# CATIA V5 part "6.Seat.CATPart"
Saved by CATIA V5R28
Part number: Seat
Bounding box of the stored display mesh (mm): x -115 to 115, y -85.091 to 85.091, z -146.629 to 45.921
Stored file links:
  D:\Catia Cycle design\6.Seat.CATPart
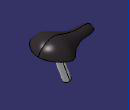
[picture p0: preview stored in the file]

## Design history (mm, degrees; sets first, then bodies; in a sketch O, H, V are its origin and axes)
Set1
  Sketch1 on xy-plane, origin (0, 0, 0), H (1, 0, 0), V (0, 1, 0)
    construction line L1 (115, 85) -> (115, -85)
    construction line L2 (115, -85) -> (-115, -85)
    construction line L3 (-115, -85) -> (-115, 85)
    construction line L4 (-115, 85) -> (115, 85)
    construction line L5 (-115, 85) -> (115, -85)
    construction line L6 (-115, -85) -> (115, 85)
    construction line L7 (-115, 0) -> (115, 0)
    point P5 (-115, 0)
    point P6 (115, 0)
    axis line L8 (0, 85) -> (0, -85)
    point P7 (0, 85)
    point P8 (0, -85)
    spline S1 through (-115, 0) (-108, -16) (-75, -25.5) (-40, -30) (-15, -40) (15, -60) (50, -85) (87.9412, -65) (109, -30) (115, 0)
    spline S2 through (-115, 0) (-108, 16) (-75, 25.5) (-40, 30) (-15, 40) (15, 60) (50, 85) (87.9412, 65) (109, 30) (115, 0)
    point P9 (-115, 0)
    point P10 (-40, -30)
    point P11 (50, -85)
    point P12 (87.9412, -65)
    point P13 (115, 0)
    point P14 (-108, -16)
    point P15 (-75, -25.5)
    point P16 (-15, -40)
    point P17 (15, -60)
    point P18 (109, -30)
    point P19 (115, 0)
    point P20 (-115, 0)
    point P21 (109, 30)
    point P22 (87.9412, 65)
    point P23 (50, 85)
    point P24 (15, 60)
    point P25 (-15, 40)
    point P26 (-40, 30)
    point P27 (-75, 25.5)
    point P28 (-108, 16)
    length L4 = 230
    length L1 = 170
    distance P14 L7 = 16
    distance P14 L3 = 7
    distance P15 L7 = 25.5
    distance P15 L3 = 40
    distance P10 L7 = 30
    distance P10 L3 = 75
    distance P16 L7 = 40
    distance P16 L3 = 100
    distance P17 L7 = 60
    distance P17 L3 = 130
    distance P11 L1 = 65
    distance P12 L7 = 65
    distance P18 L7 = 30
    distance P18 L1 = 6
    vertical: L1 V, L3 V, L8 V
    horizontal: L2 H, L4 H, L7 H
    equidistance: L1 L3 O, L2 L4 O
    midpoint: P5 L3, P6 L1, P7 L4, P8 L2
    coincidence: P9 P5, P11 L2, P12 L5, P13 P6
    symmetry: S1 S2 L7, P13 P19 L7, P9 P20 L7, P18 P21 L7, P12 P22 L7, P11 P23 L7, P17 P24 L7, P16 P25 L7, P10 P26 L7, P15 P27 L7, P14 P28 L7
  Sketch2 on zx-plane, origin (0, 0, 0), H (-1, 0, 0), V (0, 0, 1)
    spline S1 through (115, 0) (100, 18) (65, 21) (19, 25) (-14, 36) (-46, 45) (-85, 36) (-115, 0)
    reference projected line E1 (-115, 0) -> (115, 0) from Sketch1.S2
    reference projected line E2 (-115, 0) -> (115, 0) from Sketch1.S2
    reference projected line E3 (-115, 0) -> (115, 0) from Sketch1.S2
    reference projected line E4 (-115, 0) -> (115, 0) from Sketch1.S2
    reference projected line E5 (-115, 0) -> (115, 0) from Sketch1.S2
    reference projected line E6 (-115, 0) -> (115, 0) from Sketch1.S2
    reference projected line E7 (-115, 0) -> (115, 0) from Sketch1.S2
    point P1 (115, 0)
    point P2 (-115, 0)
    point P3 (-85, 36)
    point P4 (-46, 45)
    point P5 (-14, 36)
    point P6 (19, 25)
    point P7 (65, 21)
    point P8 (100, 18)
    distance V P2 = 115
    distance P3 E1 = 36
    distance P3 V = 85
    distance P4 E2 = 45
    distance P4 V = 46
    distance P5 V = 14
    distance P5 E3 = 36
    distance P6 V = 19
    distance P6 E4 = 25
    distance P7 E5 = 21
    distance P7 V = 65
    distance P8 E6 = 18
    distance P8 V = 100
    distance V P1 = 115
    distance P1 E7 = 0
    coincidence: P2 H
  DatumCurve1
  DatumCurve2
  Line1: type PtPt, FirstPoint Sketch2.P1, SecondPoint Sketch2.P2
  Plane1: type Offset, RefPlane yz-plane, Offset 108
  Plane2: type Offset, RefPlane yz-plane, Offset 80
  Plane3: type Offset, RefPlane yz-plane, Offset 50
  Plane4: type Offset, RefPlane yz-plane, Offset 40, reversed
  Plane5: type Offset, RefPlane yz-plane, Offset 80, reversed
  Plane6: type Offset, RefPlane yz-plane, Offset 110, reversed
  MultiSel1
  Sketch3 on Plane1, origin (108, 0, 0), H (0, 1, 0), V (0, 0, 1)
    arc A1 centre (0, -28.3932) radius 43.2124 from (-32.5751, 0) to (0, 14.8192) cw
    point P2 (-32.5751, 0)
    point P3 (0, 14.8192)
    reference projected point E1 (0, 14.8192) from {intersect ToIntersect1 Sketch2, ToIntersect2 Plane1}
    reference projected point E2 (-32.5751, 0) from {intersect ToIntersect1 DatumCurve2, ToIntersect2 Plane1}
    axis line L1 (0, 14.8192) -> (33.2132, 14.8192)
    line L2 (-32.5751, 0) -> (0, 0)
    line L3 (0, 0) -> (0, 14.8192)
    coincidence: P2 H, P3 V, P3 E1, P2 E2
    horizontal: L1 H, L2 H
    tangency: A1 L1
    vertical: L3 V
  MultiSel2
  Sketch4 on Plane3, origin (50, 0, 0), H (0, 1, 0), V (0, 0, 1)
    arc A1 centre (-0.0002, -57.2359) radius 102.474 from (-85, 0) to (0, 45.2381) cw
    point P2 (-85, 0)
    point P3 (0, 45.2381)
    reference projected point E1 (0, 45.2381) from {intersect ToIntersect1 Sketch2, ToIntersect2 Plane3}
    reference projected point E2 (-85, 0) from {intersect ToIntersect1 DatumCurve2, ToIntersect2 Plane3}
    axis line L1 (0, 45.2381) -> (37.5045, 45.2381)
    line L2 (-85, 0) -> (0, 0)
    line L3 (0, 0) -> (0, 45.2381)
    coincidence: P2 H, P3 V, P3 E1, P2 E2
    horizontal: L1 H, L2 H
    tangency: L1 A1
    vertical: L3 V
  MultiSel3
  Sketch5 on Plane2, origin (80, 0, 0), H (0, 1, 0), V (0, 0, 1)
    arc A1 centre (-0.0001, -48.922) radius 87.5263 from (-72.5776, 0) to (0, 38.6043) cw
    point P2 (-72.5776, 0)
    point P3 (0, 38.6043)
    reference projected point E1 (0, 38.6043) from {intersect ToIntersect1 Sketch2, ToIntersect2 Plane2}
    reference projected point E2 (-72.5776, 0) from {intersect ToIntersect1 DatumCurve2, ToIntersect2 Plane2}
    axis line L1 (-0.0001, 38.6043) -> (30.8614, 38.6043)
    point P4 (-0.0001, 38.6043)
    line L2 (-72.5776, 0) -> (0, 0)
    line L3 (0, 0) -> (0, 38.6043)
    coincidence: P2 H, P3 V, E1 P3, P2 E2, P4 A1
    horizontal: L1 H, L2 H
    tangency: L1 A1
    vertical: L3 V
  MultiSel4
  Sketch6 on Plane5, origin (-80, 0, 0), H (0, 1, 0), V (0, 0, 1)
    point P1 (-25.0641, 0)
    arc A1 centre (0, -3.9144) radius 25.3679 from (-25.0641, 0) to (0, 21.4535) cw
    point P3 (0, 21.4535)
    reference projected point E1 (0, 21.4535) from {intersect ToIntersect1 Sketch2, ToIntersect2 Plane5}
    reference projected point E2 (-25.0641, 0) from {intersect ToIntersect1 DatumCurve2, ToIntersect2 Plane5}
    axis line L1 (0, 21.4535) -> (15.3574, 21.4535)
    line L2 (-25.0641, 0) -> (0, 0)
    line L3 (0, 0) -> (0, 21.4535)
    coincidence: P3 V, P3 E1, E2 P1
    horizontal: L1 H, L2 H
    tangency: A1 L1
    vertical: L3 V
  Intersect1: ToIntersect1 Sketch2, ToIntersect2 DatumCurve2
  MultiSel5
  Sketch7 on Plane4, origin (-40, 0, 0), H (0, 1, 0), V (0, 0, 1)
    arc A1 centre (-0.0001, -10.2366) radius 31.6983 from (-30, 0) to (0, 21.4617) cw
    point P2 (-30, 0)
    point P3 (0, 21.4617)
    reference projected point E1 (-30, 0) from {intersect ToIntersect1 DatumCurve2, ToIntersect2 Plane4}
    reference projected point E2 (0, 21.4617) from {intersect ToIntersect1 Sketch2, ToIntersect2 Plane4}
    axis line L1 (0, 21.4617) -> (15.7566, 21.4617)
    point P5 (-30, 0)
    line L2 (-30, 0) -> (0, 0)
    line L3 (0, 0) -> (0, 21.4617)
    coincidence: P2 H, P3 V, P2 E1, P3 E2, P5 A1, P5 H
    horizontal: L1 H, L2 H
    tangency: L1 A1
    vertical: L3 V
  MultiSel6
  Sketch8 on Plane6, origin (-110, 0, 0), H (0, 1, 0), V (0, 0, 1)
    arc A1 centre (0, -4.828) radius 14.8378 from (-14.0304, 0) to (0, 10.0098) cw
    point P2 (-14.0304, 0)
    point P3 (0, 10.0098)
    reference projected point E1 (0, 10.0098) from {intersect ToIntersect1 Sketch2, ToIntersect2 Plane6}
    reference projected point E2 (-14.0304, 0) from {intersect ToIntersect1 DatumCurve2, ToIntersect2 Plane6}
    axis line L1 (0, 10.0098) -> (19.8404, 10.0098)
    line L2 (-14.0304, 0) -> (0, 0)
    line L3 (0, 0) -> (0, 10.0098)
    coincidence: P2 H, P3 V, P3 E1, P2 E2
    horizontal: L1 H, L2 H
    tangency: L1 A1
    vertical: L3 V
  MultiSel7
  Sketch9 on yz-plane, origin (0, 0, 0), H (0, 1, 0), V (0, 0, 1)
    arc A1 centre (0, -23.0233) radius 53.8585 from (-48.6895, 0) to (0, 30.8352) cw
    point P2 (0, 30.8352)
    point P3 (-48.6895, 0)
    reference projected point E1 (0, 30.8352) from {intersect ToIntersect1 Sketch2, ToIntersect2 yz-plane}
    reference projected point E2 (-48.6895, 0) from {intersect ToIntersect1 DatumCurve2, ToIntersect2 yz-plane}
    axis line L1 (0, 30.8352) -> (19.6242, 30.8352)
    line L2 (-48.6895, 0) -> (0, 0)
    line L3 (0, 0) -> (0, 30.8352)
    coincidence: P2 V, P2 E1, P3 E2
    tangency: L1 A1
    horizontal: L1 H, L2 H
    vertical: L3 V
  Loft1: Sections (Sketch3; Sketch5; Sketch4; Sketch9; Sketch7; Sketch6; Sketch8), Guides (Sketch2; Line1; DatumCurve2)
  Loft2: Sections Sketch8, Guides (Line1; Sketch2; DatumCurve2)
Body1 (main body)
  CloseSurface1: CloseElement Loft2
  Mirror1: of CloseSurface1, about zx-plane
  Sketch10 on zx-plane, origin (0, 0, 0), H (-1, 0, 0), V (0, 0, 1)
    point P1 (-19, 20)
    line L1 (-19, 20) -> (-8.8103, -27.939)
    line L2 (-8.8103, -27.939) -> (-63.9586, -27.939)
    line L3 (-63.9586, -27.939) -> (-85.3185, -4.1379)
    line L4 (-85.3185, -4.1379) -> (-19, 20)
    reference projected line E1 (115, 0) -> (-115, 0) from edge [face of CloseSurface1 | face of CloseSurface1]
    reference projected line E2 (115, 0) -> (-115, 0) from edge [face of CloseSurface1 | face of CloseSurface1]
    angle L1 L4 = 82
    angle L4 E1 = 20
    distance P1 V = 19
    distance P1 E2 = 20
    horizontal: L2 H
  Pocket1: profile Sketch10, direction (0, -1, 0), length 35, mirrored extent
  Sketch11 on face of Pocket1 from Sketch10.L4, origin (8.6505, 0, 23.7669), H (0, -1, 0), V (-0.9397, 0, 0.342)
    circle A1 centre (0, -41.8594) radius 14
    point P1 (0, -41.8594)
    reference projected line E1 (35, -13.8594) -> (-35, -13.8594) from edge [face of CloseSurface1 | face of Pocket1 from Sketch10.L1]
    radius A1 = 14
    distance P1 E1 = 28
    coincidence: P1 V
  Pad1: profile Sketch11, direction (-0.342, 0, -0.9397), length 161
